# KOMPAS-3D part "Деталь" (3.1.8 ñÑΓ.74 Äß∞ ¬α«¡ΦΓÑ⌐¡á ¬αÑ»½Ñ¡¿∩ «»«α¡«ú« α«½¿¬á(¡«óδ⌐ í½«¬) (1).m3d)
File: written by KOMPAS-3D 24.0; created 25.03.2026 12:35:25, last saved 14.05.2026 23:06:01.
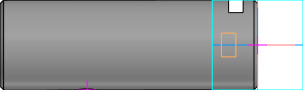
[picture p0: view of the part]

Document properties: Автор: TMK; Полное имя файла: E:\test_kompas\all_v22\3.1.8 дет.74 Ось кронштейна крепления опорного ролика(новый блок) (1).m3d; Организация: TMK

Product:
- Part/product: Деталь
    Масса: 2.046242

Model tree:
1. Эскиз:1
2. Элемент выдавливания:1
     Расстояние 2 = 142
3. Фаска:1  (with: Ребро.Элемент выдавливания:1)
     Угол = 45; Длина 1 = 2; Длина 2 = 2
4. Эскиз:2
5. Отверстие:2  (with: Грань.Элемент выдавливания:1)
     Глубина выреза = 99.5; Диаметр отверстия = 11.4448; Угол конуса дна = 118; Диаметр цековки = 23; Глубина цековки = 12
6. G 1/4  (with: Грань.Отверстие:2)
     Длина резьбы = 20; Шаг резьбы = 1.337; Номинальный диаметр резьбы = 13.157
7. Фаска:2  (with: Ребро.Отверстие:2)
     Угол = 45; Длина 1 = 1.6; Длина 2 = 1.6
8. Смещенная плоскость:2
     Расстояние = 25
9. Эскиз:4
10. Отверстие:3
     Глубина выреза = 30.5; Диаметр отверстия = 11.5; Угол конуса дна = 118; Расстояние 2 = -94
11. Смещенная плоскость:3
     Расстояние = 25
12. Эскиз:5
13. Элемент выдавливания:3
     Расстояние 2 = 50

Expressions: cil2_6357-81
